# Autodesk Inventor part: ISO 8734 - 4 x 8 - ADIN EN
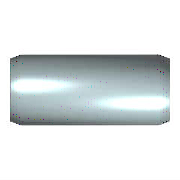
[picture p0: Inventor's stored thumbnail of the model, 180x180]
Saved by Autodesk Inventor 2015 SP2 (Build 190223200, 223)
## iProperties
IsCustomPart: 1
Created: 2012-02
Part Number: ISO 8734 - 4 x 8 - ADIN EN
Material: Stahl
Description: Zylinderstift
Document SubType Name: Modeling
Standard: ISO 8734
Designer: rYan
Standards Organization: DIN
Language: de-DE
Size Designation: 4 x 10 - A
Categories: <MemberInstance><Categories><Category DisplayName="Verbindungselemente" InternalName="e4da775c-781d-43d5-af7c-5136215cf5a6" Mnemonic="FSTN"><Category DisplayNam
Density: 7.85 g/cm^3
Mass: 0.778972 g
Surface Area: 1.21467 cm^2
Volume: 0.0992321 cm^3
Appearance: Platte
Author: rYan
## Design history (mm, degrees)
sketch "Skizze"
  geometry: C1 r 2 at (0, 0); 1 further point
  constraints: 1 centre point, 1 coincident
  dimensions: "d1" = 4 diameter of C1 (= NND)
extrude "Körper" new body sketch "Skizze" distance "d2" = 8 (= NLG); taper "d3" = 0 deg
body "Solid1"
chamfer "Fase1" distance "d4" = 0.63 (= PHH); stored, may be unused: angle "d5" = 15 deg (= FAWI), second distance "d11" = 0.63 (= PHH)
chamfer "Fase2" distance "d8" = 0.63 (= PHH); stored, may be unused: angle "d9" = 15 deg (= FAWI), second distance "d12" = 0.63 (= PHH)
other parameters: "NND" = 4 [user parameter; used in 1 equation term], "NLG" = 8 [user parameter; used in 1 equation term], "PHH" = 0.63 [user parameter; used in 5 equation terms], "FAWI" = 15 deg [user parameter; used in 2 equation terms], "d13" = 0, "d15" = 0, "d16" = 0, "PHH2" = 0.63 (= PHH) [user parameter], "FAWI2" = 15 deg [user parameter]
